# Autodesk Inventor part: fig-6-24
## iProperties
Created: 2005-04
Part Number: fig-6-24
Document SubType Name: Modeling
Designer: CADCIM
Density: 1 g/cm^3
Author: CADCIM
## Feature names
1. Extrusion1
2. Extrusion2
